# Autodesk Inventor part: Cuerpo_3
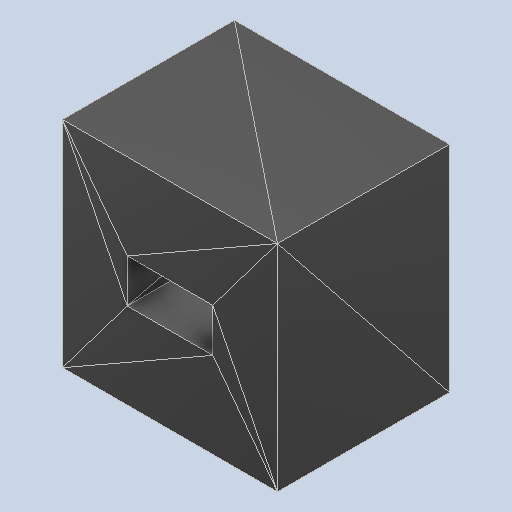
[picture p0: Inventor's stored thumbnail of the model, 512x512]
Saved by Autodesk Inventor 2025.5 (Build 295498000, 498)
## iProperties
Created: 2026-10
Part Number: Cuerpo_3
Material: Genérico
Document SubType Name: Modeling
Designer: Luis M
Density: 1 g/cm^3
Appearance: Valor por defecto
Author: Luis M
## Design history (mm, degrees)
feature "Base1"
node "Sólido1"
